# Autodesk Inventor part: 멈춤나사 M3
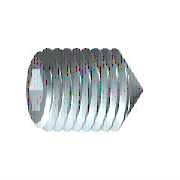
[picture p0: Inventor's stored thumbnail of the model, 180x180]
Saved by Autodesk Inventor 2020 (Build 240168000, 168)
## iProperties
Created: 2012-02
Part Number: 멈춤나사 M3
Material: 강철, 연강
Description: 6각 소켓 머리 없는 멈춤 나사
Document SubType Name: Modeling
Standard: KS B 1028
Designer: mduedu
Standards Organization: KS
Language: ko-KR
Size Designation: 원추점 M3x8
Categories: <MemberInstance><Categories><Category DisplayName="조임쇠" InternalName="e4da775c-781d-43d5-af7c-5136215cf5a6" Mnemonic="FSTN"><Category DisplayName="볼트" InternalN
Density: 7.86 g/cm^3
Mass: 0.360339 g
Surface Area: 0.888172 cm^2
Volume: 0.0458447 cm^3
Appearance: 강철
IsCustomPart: 1
Author: mduedu
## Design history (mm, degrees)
sketch "스케치1"
  geometry: L1 (0, 0)-(5.5, 0); L2 (8, 0.866)-(8, 1.5); L3 (8, 1.5)-(0, 1.5); L4 (8, 0.866)-(6, 0.866); L5 (6, 0.866)-(5.5, 0); L6 (0, -0.3)-(0, 1.8) reference; L7 (0, 1.5)-(0, 0)
  constraints: 13 end point, 3 parallel, 1 collinear, 1 perpendicular, 1 point on line
  dimensions: "d0" = 2 distance of L2.start L4.end (= INTI); "d1" = 60 deg angle of L5 L1; "d2" = 3 diameter of L3 L1 (= NND); "d3" = 1.73205 diameter of L4 L1 (= 1.1547 x SW); "d5" = 8 distance from line of L2 L3.end (= NLG)
revolve "본체" sketch "스케치1" stored, may be unused: angle "d6" = 90 deg
sketch "스케치2"
  geometry: L1 (-0.433, 0.75)-(0.433, 0.75); L2 (0.433, 0.75)-(0.866, 0); L3 (0.866, 0)-(0.433, -0.75); L4 (0.433, -0.75)-(-0.433, -0.75); L5 (-0.433, -0.75)-(-0.866, 0); L6 (-0.866, 0)-(-0.433, 0.75); 3 further points
  constraints: 12 end point, 1 coincident, 1 horizontal, 13 other
extrude "슬롯" join sketch "스케치2" taper "d7" = 0 deg; stored distance "d21" = 10
workaxis "Work Axis1"
workplane "Work Plane1"
sketch "스케치5"
  geometry: L1 (-4, -0.15)-(-2.65, -1.5) reference; L2 (-4, 0.15)-(-2.65, 1.5) reference; L3 (-2.65, 1.5)-(-4.15, 0); L4 (-2.65, -1.5)-(-4.15, 0); 1 further point
  constraints: 4 end point, 1 horizontal alignment, 1 perpendicular
node "작업점1"
body "Solid1"
feature "스레드" dims "d12" = 8 (= NLG), "d13" = 0
chamfer "모따기1" distance "d8" = 1.35 (computed from NND, SPD, FAWI); stored, may be unused: angle "d9" = 45 deg (= FAWI), second distance "d34" = 1.35 (computed from NND, SPD, FAWI)
chamfer "모따기2" distance "d10" = 0.30673 (= -0.5 x GD1 + 0.5 x NND); stored, may be unused: angle "d11" = 45 deg (= FAWI), second distance "d35" = 0.30673 (= -0.5 x GD1 + 0.5 x NND)
other parameters: "NND" = 3 [user parameter; used in 5 equation terms], "NLG" = 8 [user parameter; used in 2 equation terms], "INTI" = 2 [user parameter; used in 1 equation term], "FAWI" = 45 deg [user parameter; used in 4 equation terms], "SW" = 1.5 [user parameter; used in 2 equation terms], "GD1" = 2.38655 (= THREADDIA - 1.2269 x PTC) [user parameter; used in 2 equation terms], "d4" = 0, "FAWI1" = 45 deg [user parameter], "SPD" = 0.3 [user parameter; used in 2 equation terms], "d36" = 0, "d37" = 0, "GUL" = 0.30673 (= 0.61345 x PTC) [user parameter], "TOA" = 30 deg [user parameter], "THREADDIA" = 3 [user parameter; used in 1 equation term], "PTC" = 0.5 [user parameter; used in 4 equation terms], "GAL" = 0.30673 (= 0.61345 x PTC) [user parameter], "E0" = 1.7325 (= 1.155 x SW) [user parameter]
